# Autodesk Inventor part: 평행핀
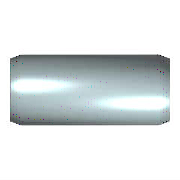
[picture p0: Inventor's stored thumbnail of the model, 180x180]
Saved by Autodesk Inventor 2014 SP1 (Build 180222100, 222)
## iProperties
IsCustomPart: 0
Created: 2009-02
Part Number: 평행핀
Material: 강, 연강
Description: 평행 핀
Document SubType Name: Modeling
Standard: KS B 1320
Designer: KYOUNG IL JANG
Standards Organization: KS
Language: ko-KR
Size Designation: B 5 x  20
Categories: <MemberInstance><Categories><Category DisplayName="조임쇠" InternalName="e4da775c-781d-43d5-af7c-5136215cf5a6" Mnemonic="FSTN"><Category DisplayName="핀" InternalNa
Density: 1 g/cm^3
Appearance: 강철
Author: KYOUNG IL JANG
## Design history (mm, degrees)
sketch "스케치"
  geometry: C1 r 2.5 at (0, 0); 1 further point
  constraints: 1 centre point, 1 coincident
  dimensions: "d1" = 5 diameter of C1 (= NND)
extrude "본체" new body sketch "스케치" distance "d2" = 20 (= NLG); taper "d3" = 0 deg
chamfer "스케치2" distance "d8" = 0.8 (= PHH); stored, may be unused: angle "d9" = 15 deg (= FAWI), second distance "d12" = 0.8 (= PHH)
body "Solid1"
chamfer "모따기1" distance "d4" = 0.8 (= PHH); stored, may be unused: angle "d5" = 15 deg (= FAWI), second distance "d11" = 0.8 (= PHH)
other parameters: "NND" = 5 [user parameter; used in 1 equation term], "NLG" = 20 [user parameter; used in 1 equation term], "PHH" = 0.8 [user parameter; used in 4 equation terms], "FAWI" = 15 deg [user parameter; used in 2 equation terms], "d13" = 0, "d15" = 0, "d16" = 0, "KAH" = 0.63 [user parameter]
